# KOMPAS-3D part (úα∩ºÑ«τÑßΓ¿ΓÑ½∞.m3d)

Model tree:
1. Эскиз:1
2. Операция выдавливания:1
     Расстояние 1 = 4
3. Эскиз:2
4. Вырезать элемент выдавливания:1
     Расстояние 1 = 4
5. Эскиз:3
6. Вырезать элемент выдавливания:3
     Расстояние 1 = 3
7. Эскиз:5
8. Вырезать элемент выдавливания:4
     Расстояние 1 = 4
9. Скругление:6
     Радиус = 1
10. Скругление:7
     Радиус = 1
11. Скругление:8
     Радиус = 0.2
12. Скругление:9
     Радиус = 0.2

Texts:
  Сплав АЛ8  ГОСТ 1583-93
